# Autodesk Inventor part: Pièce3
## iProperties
Shininess: 64.0
Length Units: 11269
Angle Units: 11279
Time Units: 11290
Mass Units: 11283
Length Display Precision: 3
Angle Display Precision: 2
Compacted: True
Part Number: Pièce3
Document SubType Name: Modeling
Created: 2004-06
Material: Par défaut
Designer: laurent
Density: 0.0
Volumn: 0.0
Area: 0.0
PropertySet Name: Model Information
Control State: 0
Master: False
Checked Out: False
Author: laurent
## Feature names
1. Extrusion1
2. Balayage1
